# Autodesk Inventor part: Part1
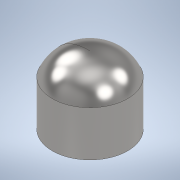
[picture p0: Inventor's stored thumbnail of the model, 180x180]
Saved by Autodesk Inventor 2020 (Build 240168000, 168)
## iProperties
Created: 2019-08
Part Number: Part1
Material: Stainless Steel
Document SubType Name: Modeling
Designer: Synergysoft
Density: 8 g/cm^3
Appearance: Semi-Polished
Author: Synergysoft
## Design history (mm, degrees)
sketch "Sketch1"
  geometry: C1 r 25 at (0, 0); 1 further point
  constraints: 1 centre point, 1 coincident
  dimensions: "d0" = 50 diameter of C1
extrude "Extrusion1" new body sketch "Sketch1" distance "d1" = 30; taper "d2" = 0 deg
workplane "Work Plane1"
sketch "Sketch2"
  geometry: C1 r 25 at (0, 0) reference; 1 further point
loft "Loft1" sketch "Sketch2" dims "d4" = 0, "d5" = 90 deg, "d8" = 15, "d9" = 90 deg
  node "Edges1"
feature "Form1"
body "Solid1"
body "Solid2"
other parameters: "d3" = 15
